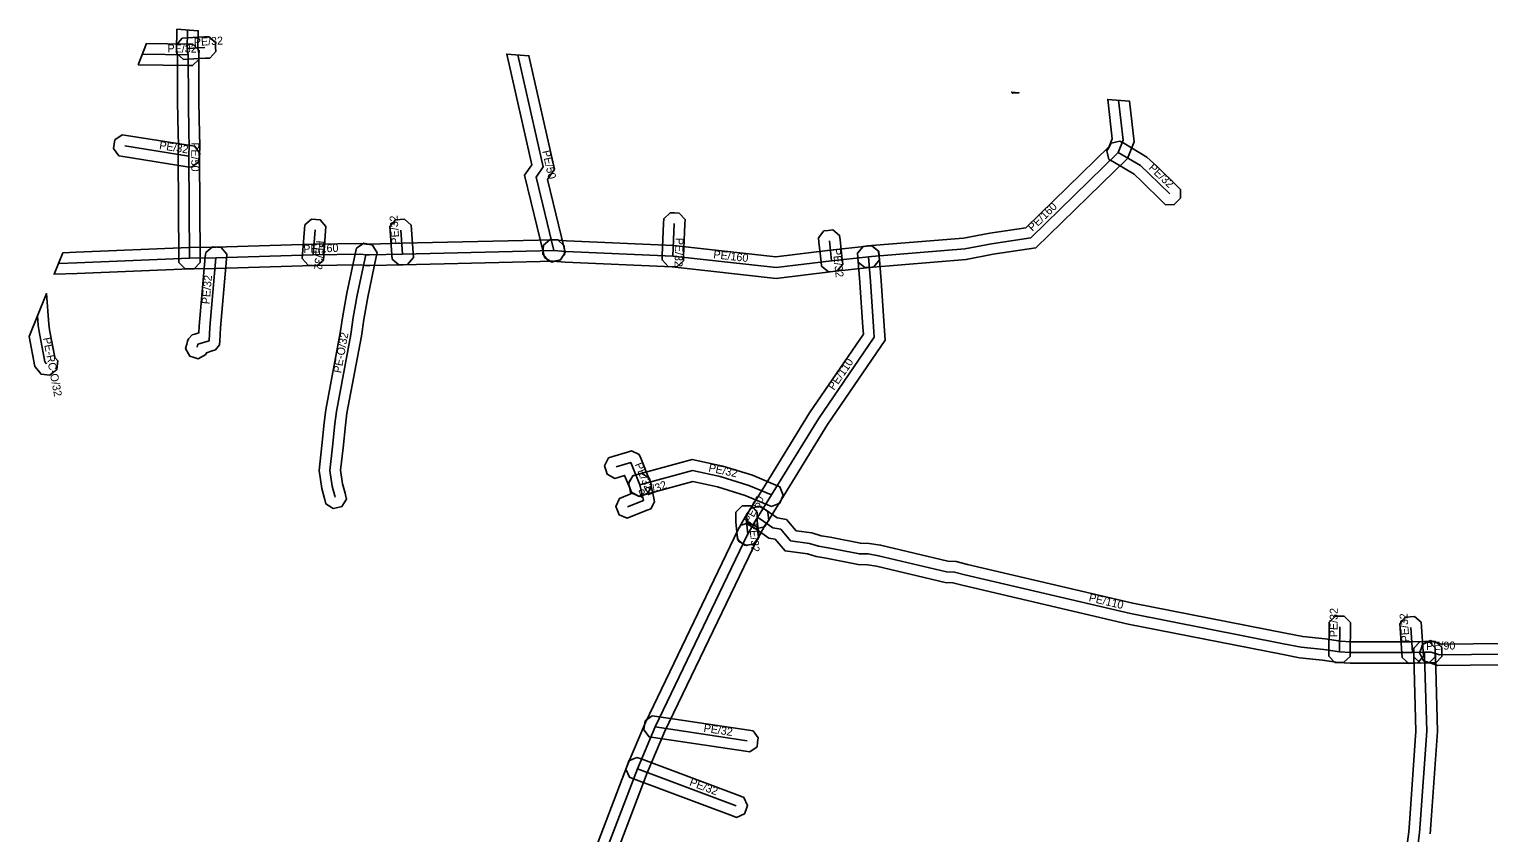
# Model space of a CAD drawing. Extents: x -772893 to -772575, y -1033735 to -1033288.
# Drawn here: x -772863.9 to -772727.1, y -1033363.2 to -1033287.9 of the extents above; entities that cross this region are included whole.
import ezdxf

# ---------------------------------------------------------------- set-up
doc = ezdxf.new("R2010")
doc.units = 0
for name, color, linetype in [('1', 7, 'Continuous'), ('24', 7, 'Continuous'), ('30', 7, 'Continuous')]:
    doc.layers.add(name, color=color, linetype=linetype)

msp = doc.modelspace()

# ---------------------------------------------------------------- linework, layer by layer
at = {"layer": '1'}
for points in [[(-772849.52, -1033288.74), (-772849.1, -1033288.72), (-772847.45, -1033288.63), (-772847.04, -1033288.61), (-772846.42, -1033289.16), (-772846.4, -1033289.58), (-772846.38, -1033289.99), (-772846.93, -1033290.61), (-772847.35, -1033290.63), (-772849, -1033290.72), (-772849.41, -1033290.74), (-772850.03, -1033290.19), (-772850.05, -1033289.77), (-772850.07, -1033289.36)], [(-772850.02, -1033288.08), (-772850.02, -1033287.9), (-772848.02, -1033288.05), (-772848.02, -1033288.12), (-772848.05, -1033289.65), (-772847.96, -1033290.22), (-772847.96, -1033294.7), (-772847.9, -1033297.66), (-772847.89, -1033298.75), (-772847.92, -1033299.8), (-772847.84, -1033309.33), (-772847.84, -1033309.75), (-772848.42, -1033310.34), (-772848.83, -1033310.34), (-772849.25, -1033310.34), (-772849.84, -1033309.76), (-772849.84, -1033309.35), (-772849.92, -1033299.78), (-772849.89, -1033298.73), (-772849.9, -1033297.68), (-772849.96, -1033294.72), (-772849.96, -1033290.38), (-772850.05, -1033289.79)], [(-772853.66, -1033291.24), (-772852.86, -1033289.25), (-772848.95, -1033289.3), (-772848.53, -1033289.31), (-772847.95, -1033289.9), (-772847.96, -1033290.31), (-772847.96, -1033290.73), (-772848.56, -1033291.31), (-772848.97, -1033291.3)], [(-772816.78, -1033300.6), (-772819.12, -1033290.23), (-772817.04, -1033290.39), (-772814.64, -1033301), (-772815.29, -1033301.97), (-772813.75, -1033308.41), (-772813.65, -1033308.81), (-772814.08, -1033309.52), (-772814.49, -1033309.61), (-772814.89, -1033309.71), (-772815.59, -1033309.28), (-772815.69, -1033308.87), (-772817.45, -1033301.57)], [(-772771.7, -1033293.9), (-772771.81, -1033293.8), (-772771.13, -1033293.86), (-772771.29, -1033293.87)], [(-772762.39, -1033298.16), (-772762.81, -1033294.48), (-772760.77, -1033294.64), (-772760.34, -1033298.44), (-772760.97, -1033300.02), (-772769.54, -1033308.38), (-772773.53, -1033308.99), (-772776.06, -1033309.46), (-772785.15, -1033310.21), (-772785.56, -1033310.24), (-772786.19, -1033309.71), (-772786.23, -1033309.29), (-772786.26, -1033308.88), (-772785.73, -1033308.25), (-772785.31, -1033308.21), (-772776.32, -1033307.47), (-772773.86, -1033307.02), (-772770.48, -1033306.5), (-772762.67, -1033298.88)], [(-772848.67, -1033300.84), (-772849.08, -1033300.78), (-772855.07, -1033299.83), (-772855.48, -1033299.76), (-772855.96, -1033299.09), (-772855.9, -1033298.68), (-772855.83, -1033298.27), (-772855.16, -1033297.79), (-772854.75, -1033297.85), (-772848.76, -1033298.8), (-772848.35, -1033298.87), (-772847.87, -1033299.54), (-772847.93, -1033299.95), (-772848, -1033300.36)], [(-772761.67, -1033298.38), (-772761.31, -1033298.59), (-772759.14, -1033299.88), (-772758.22, -1033300.74), (-772756.3, -1033302.61), (-772756, -1033302.91), (-772755.99, -1033303.73), (-772756.29, -1033304.03), (-772756.58, -1033304.33), (-772757.4, -1033304.34), (-772757.7, -1033304.05), (-772759.6, -1033302.18), (-772760.34, -1033301.48), (-772762.33, -1033300.31), (-772762.69, -1033300.1), (-772762.89, -1033299.3), (-772762.68, -1033298.94), (-772762.47, -1033298.58)], [(-772802.41, -1033305.74), (-772802.43, -1033306.16), (-772802.56, -1033309.19), (-772802.57, -1033309.6), (-772803.18, -1033310.16), (-772803.6, -1033310.15), (-772804.01, -1033310.13), (-772804.57, -1033309.52), (-772804.56, -1033309.1), (-772804.43, -1033306.07), (-772804.41, -1033305.66), (-772803.8, -1033305.1), (-772803.39, -1033305.11), (-772802.97, -1033305.13)], [(-772836.06, -1033306.37), (-772836.09, -1033306.79), (-772836.25, -1033309.11), (-772836.28, -1033309.53), (-772836.91, -1033310.07), (-772837.32, -1033310.04), (-772837.73, -1033310.01), (-772838.28, -1033309.39), (-772838.25, -1033308.97), (-772838.08, -1033306.64), (-772838.05, -1033306.23), (-772837.43, -1033305.69), (-772837.01, -1033305.72), (-772836.6, -1033305.75)], [(-772829.86, -1033309.44), (-772829.89, -1033309.03), (-772830.04, -1033306.8), (-772830.07, -1033306.39), (-772829.53, -1033305.76), (-772829.11, -1033305.73), (-772828.7, -1033305.71), (-772828.07, -1033306.25), (-772828.05, -1033306.66), (-772827.89, -1033308.89), (-772827.86, -1033309.3), (-772828.41, -1033309.93), (-772828.82, -1033309.96), (-772829.23, -1033309.99)], [(-772789.63, -1033310.11), (-772789.67, -1033309.7), (-772789.88, -1033307.85), (-772789.92, -1033307.44), (-772789.4, -1033306.79), (-772788.99, -1033306.75), (-772788.58, -1033306.7), (-772787.93, -1033307.22), (-772787.89, -1033307.63), (-772787.69, -1033309.49), (-772787.64, -1033309.9), (-772788.16, -1033310.54), (-772788.57, -1033310.59), (-772788.98, -1033310.63)], [(-772859.38, -1033310.8), (-772861.53, -1033310.86), (-772860.71, -1033308.84), (-772859.45, -1033308.8), (-772848.87, -1033308.34), (-772846.39, -1033308.32), (-772837.27, -1033308.04), (-772832.73, -1033307.97), (-772832.26, -1033308.03), (-772831.98, -1033308.03), (-772828.91, -1033307.96), (-772814.74, -1033307.64), (-772814.33, -1033307.63), (-772813.73, -1033308.2), (-772813.72, -1033308.62), (-772813.71, -1033309.03), (-772814.28, -1033309.63), (-772814.7, -1033309.64), (-772828.87, -1033309.96), (-772831.96, -1033310.03), (-772832.38, -1033310.03), (-772832.84, -1033309.97), (-772837.23, -1033310.04), (-772846.35, -1033310.32), (-772848.81, -1033310.34)], [(-772831.26, -1033308.84), (-772831.34, -1033309.24), (-772832.15, -1033313), (-772832.51, -1033315.08), (-772832.74, -1033316.65), (-772834.09, -1033323.87), (-772834.24, -1033324.99), (-772834.46, -1033327.12), (-772834.69, -1033329.21), (-772834.5, -1033330.5), (-772834.25, -1033331.36), (-772834.22, -1033331.52), (-772834.12, -1033331.92), (-772834.56, -1033332.62), (-772834.96, -1033332.71), (-772835.37, -1033332.81), (-772836.07, -1033332.37), (-772836.16, -1033331.96), (-772836.19, -1033331.86), (-772836.46, -1033330.92), (-772836.71, -1033329.25), (-772836.44, -1033326.9), (-772836.22, -1033324.77), (-772836.07, -1033323.55), (-772834.72, -1033316.33), (-772834.49, -1033314.76), (-772834.11, -1033312.62), (-772833.3, -1033308.82), (-772833.21, -1033308.42), (-772832.52, -1033307.96), (-772832.11, -1033308.05), (-772831.7, -1033308.14)], [(-772784.71, -1033310.16), (-772785.12, -1033310.21), (-772788.56, -1033310.59), (-772793.89, -1033311.24), (-772803.63, -1033310.15), (-772813.65, -1033309.74), (-772814.81, -1033309.64), (-772815.22, -1033309.6), (-772815.75, -1033308.97), (-772815.72, -1033308.55), (-772815.68, -1033308.14), (-772815.05, -1033307.61), (-772814.63, -1033307.64), (-772813.53, -1033307.74), (-772803.48, -1033308.15), (-772793.9, -1033309.23), (-772788.8, -1033308.6), (-772785.34, -1033308.22), (-772784.93, -1033308.17), (-772784.28, -1033308.69), (-772784.24, -1033309.1), (-772784.19, -1033309.51)], [(-772846.71, -1033318.04), (-772847.25, -1033318.21), (-772847.3, -1033318.37), (-772848.03, -1033318.77), (-772848.42, -1033318.65), (-772848.82, -1033318.53), (-772849.22, -1033317.8), (-772849.1, -1033317.41), (-772849.02, -1033317.14), (-772848.95, -1033316.9), (-772848.6, -1033316.54), (-772848.36, -1033316.47), (-772847.97, -1033316.34), (-772847.94, -1033315.73), (-772847.37, -1033309.23), (-772847.33, -1033308.82), (-772846.7, -1033308.29), (-772846.28, -1033308.32), (-772845.87, -1033308.36), (-772845.34, -1033308.99), (-772845.37, -1033309.41), (-772845.94, -1033315.87), (-772846.01, -1033317.14), (-772846.03, -1033317.46), (-772846.41, -1033317.95)], [(-772784.27, -1033308.72), (-772784.23, -1033309.13), (-772784.04, -1033311.48), (-772783.75, -1033315.68), (-772783.66, -1033317.03), (-772789.08, -1033324.94), (-772793.45, -1033332.05), (-772794.76, -1033334.18), (-772794.98, -1033334.53), (-772795.78, -1033334.72), (-772796.14, -1033334.5), (-772796.49, -1033334.28), (-772796.68, -1033333.48), (-772796.46, -1033333.12), (-772795.15, -1033331.01), (-772790.76, -1033323.85), (-772785.7, -1033316.47), (-772785.75, -1033315.82), (-772786.03, -1033311.63), (-772786.23, -1033309.29), (-772786.26, -1033308.88), (-772785.73, -1033308.25), (-772785.31, -1033308.21), (-772784.9, -1033308.18)], [(-772863.33, -1033319.49), (-772863.87, -1033316.7), (-772862.25, -1033312.66), (-772862.03, -1033315.54), (-772861.95, -1033316.06), (-772861.45, -1033318.63), (-772861.45, -1033318.64), (-772861.19, -1033318.96), (-772861.28, -1033319.78), (-772861.6, -1033320.04), (-772861.93, -1033320.3), (-772862.75, -1033320.21), (-772863.01, -1033319.89)], [(-772807.41, -1033331.35), (-772807.57, -1033330.97), (-772808.08, -1033329.7), (-772808.59, -1033329.86), (-772808.98, -1033329.98), (-772809.72, -1033329.59), (-772809.84, -1033329.19), (-772809.96, -1033328.8), (-772809.57, -1033328.06), (-772809.17, -1033327.94), (-772807.79, -1033327.52), (-772807.42, -1033327.41), (-772806.72, -1033327.74), (-772806.57, -1033328.1), (-772805.71, -1033330.21), (-772805.56, -1033330.6), (-772805.88, -1033331.36), (-772806.26, -1033331.52), (-772806.65, -1033331.67)], [(-772794.31, -1033332.61), (-772794.69, -1033332.45), (-772796.78, -1033331.57), (-772799.38, -1033330.77), (-772801.68, -1033330.28), (-772806.38, -1033331.56), (-772806.78, -1033331.66), (-772807.5, -1033331.25), (-772807.6, -1033330.85), (-772807.71, -1033330.45), (-772807.3, -1033329.73), (-772806.9, -1033329.62), (-772801.74, -1033328.22), (-772798.88, -1033328.83), (-772796.1, -1033329.69), (-772793.91, -1033330.61), (-772793.53, -1033330.77), (-772793.22, -1033331.54), (-772793.38, -1033331.92), (-772793.54, -1033332.3)], [(-772805.75, -1033329.97), (-772805.66, -1033330.37), (-772805.34, -1033331.82), (-772805.26, -1033332.18), (-772805.61, -1033332.84), (-772805.95, -1033332.97), (-772807.45, -1033333.56), (-772807.84, -1033333.71), (-772808.6, -1033333.38), (-772808.75, -1033333), (-772808.9, -1033332.61), (-772808.57, -1033331.85), (-772808.19, -1033331.7), (-772807.48, -1033331.42), (-772807.62, -1033330.81), (-772807.71, -1033330.4), (-772807.26, -1033329.7), (-772806.86, -1033329.61), (-772806.45, -1033329.52)], [(-772797.49, -1033335.71), (-772797.53, -1033335.3), (-772797.64, -1033334.07), (-772797.64, -1033333.56), (-772797.64, -1033333.15), (-772797.05, -1033332.56), (-772796.64, -1033332.56), (-772796.23, -1033332.56), (-772795.64, -1033333.15), (-772795.64, -1033333.56), (-772795.64, -1033333.97), (-772795.53, -1033335.12), (-772795.5, -1033335.53), (-772796.03, -1033336.17), (-772796.44, -1033336.21), (-772796.85, -1033336.24)], [(-772794.57, -1033333.95), (-772794.83, -1033334.28), (-772794.93, -1033334.4), (-772795.41, -1033335.27), (-772795.66, -1033335.71), (-772795.87, -1033336.07), (-772796.67, -1033336.28), (-772797.03, -1033336.08), (-772797.39, -1033335.87), (-772797.6, -1033335.07), (-772797.4, -1033334.71), (-772797.15, -1033334.28), (-772796.6, -1033333.28), (-772796.39, -1033333.03), (-772796.13, -1033332.7), (-772795.31, -1033332.61), (-772794.98, -1033332.87), (-772794.66, -1033333.13)], [(-772795.49, -1033332.57), (-772795.13, -1033332.77), (-772794.8, -1033332.96), (-772793.78, -1033333.67), (-772792.92, -1033333.83), (-772792.01, -1033334.89), (-772790.52, -1033335.09), (-772789.67, -1033335.35), (-772788.83, -1033335.49), (-772785.98, -1033336.06), (-772785.16, -1033336.07), (-772784.09, -1033336.23), (-772777.78, -1033337.74), (-772777.02, -1033337.75), (-772775.94, -1033338.05), (-772760.46, -1033341.68), (-772746.14, -1033344.48), (-772744.54, -1033344.8), (-772742.44, -1033345.02), (-772741, -1033345.23), (-772740.03, -1033345.28), (-772734.24, -1033345.28), (-772733.13, -1033345.27), (-772732.71, -1033345.27), (-772732.12, -1033345.85), (-772732.12, -1033346.27), (-772732.12, -1033346.68), (-772732.7, -1033347.27), (-772733.11, -1033347.27), (-772734.24, -1033347.28), (-772740.08, -1033347.28), (-772741.2, -1033347.23), (-772742.69, -1033347.01), (-772744.83, -1033346.78), (-772746.52, -1033346.45), (-772760.88, -1033343.63), (-772776.44, -1033339.99), (-772777.31, -1033339.75), (-772778.03, -1033339.74), (-772784.48, -1033338.2), (-772785.32, -1033338.07), (-772786.18, -1033338.06), (-772789.19, -1033337.46), (-772790.13, -1033337.3), (-772790.95, -1033337.05), (-772793.04, -1033336.77), (-772793.98, -1033335.67), (-772794.57, -1033335.57), (-772795.86, -1033334.65), (-772796.09, -1033334.53), (-772796.46, -1033334.33), (-772796.69, -1033333.53), (-772796.49, -1033333.17), (-772796.29, -1033332.8)], [(-772742.1, -1033346.63), (-772742.1, -1033346.22), (-772742.07, -1033343.88), (-772742.07, -1033343.46), (-772741.47, -1033342.89), (-772741.06, -1033342.89), (-772740.64, -1033342.9), (-772740.07, -1033343.49), (-772740.07, -1033343.9), (-772740.1, -1033346.24), (-772740.1, -1033346.66), (-772740.7, -1033347.23), (-772741.11, -1033347.23), (-772741.53, -1033347.22)], [(-772735.21, -1033346.77), (-772735.24, -1033346.35), (-772735.41, -1033344.01), (-772735.44, -1033343.6), (-772734.9, -1033342.97), (-772734.48, -1033342.94), (-772734.07, -1033342.91), (-772733.44, -1033343.46), (-772733.41, -1033343.87), (-772733.24, -1033346.21), (-772733.21, -1033346.62), (-772733.76, -1033347.25), (-772734.17, -1033347.28), (-772734.58, -1033347.31)], [(-772733.55, -1033345.28), (-772733.14, -1033345.27), (-772732.8, -1033345.27), (-772732.52, -1033345.26), (-772732.1, -1033345.25), (-772731.51, -1033345.83), (-772731.5, -1033346.24), (-772731.49, -1033346.66), (-772732.07, -1033347.25), (-772732.48, -1033347.26), (-772732.76, -1033347.27), (-772733.1, -1033347.27), (-772733.51, -1033347.28), (-772734.11, -1033346.71), (-772734.12, -1033346.29), (-772734.13, -1033345.88)], [(-772805.48, -1033352.21), (-772805.07, -1033352.27), (-772796.45, -1033353.56), (-772796.04, -1033353.62), (-772795.55, -1033354.29), (-772795.61, -1033354.7), (-772795.67, -1033355.11), (-772796.34, -1033355.6), (-772796.75, -1033355.54), (-772805.37, -1033354.25), (-772805.78, -1033354.19), (-772806.27, -1033353.52), (-772806.21, -1033353.11), (-772806.15, -1033352.7)], [(-772806.92, -1033356.11), (-772806.53, -1033356.25), (-772797.28, -1033359.71), (-772796.89, -1033359.86), (-772796.55, -1033360.61), (-772796.69, -1033361), (-772796.84, -1033361.39), (-772797.59, -1033361.73), (-772797.98, -1033361.59), (-772807.23, -1033358.13), (-772807.62, -1033357.98), (-772807.96, -1033357.23), (-772807.82, -1033356.84), (-772807.67, -1033356.45)]]:
    msp.add_lwpolyline(points, close=True, dxfattribs=at)
for points in [[(-772813.06, -1033370.57), (-772807.81, -1033356.82), (-772806.13, -1033352.85), (-772797.43, -1033334.78), (-772797.4, -1033334.71), (-772797.19, -1033334.35), (-772796.39, -1033334.14), (-772796.03, -1033334.34), (-772795.67, -1033334.55), (-772795.46, -1033335.35), (-772795.66, -1033335.71), (-772795.66, -1033335.71), (-772804.31, -1033353.67), (-772805.95, -1033357.56), (-772811.1, -1033371.05)], [(-772734.71, -1033364.01), (-772734.59, -1033363.08), (-772734.54, -1033362.28), (-772733.93, -1033353.65), (-772734.11, -1033346.6), (-772734.12, -1033346.3), (-772734.13, -1033345.88), (-772733.56, -1033345.28), (-772733.14, -1033345.27), (-772732.73, -1033345.26), (-772732.13, -1033345.84), (-772732.12, -1033346.25), (-772732.11, -1033346.55), (-772731.92, -1033353.69), (-772732.54, -1033362.42), (-772732.6, -1033363.28)], [(-772707.62, -1033347.27), (-772731.89, -1033347.52), (-772732.82, -1033347.21), (-772733.21, -1033347.07), (-772733.58, -1033346.33), (-772733.45, -1033345.94), (-772733.31, -1033345.55), (-772732.57, -1033345.18), (-772732.18, -1033345.31), (-772731.57, -1033345.52), (-772707.68, -1033345.27)]]:
    msp.add_lwpolyline(points, dxfattribs=at)
at = {"layer": '24'}
for points in [[(-772849.02, -1033287.98), (-772849.02, -1033288.1), (-772849.05, -1033289.72), (-772848.96, -1033290.3), (-772848.95, -1033294.71), (-772848.9, -1033297.67), (-772848.89, -1033298.74), (-772848.92, -1033299.79), (-772848.84, -1033309.34)], [(-772848.96, -1033290.3), (-772853.26, -1033290.25)], [(-772849.05, -1033289.72), (-772847.4, -1033289.63)], [(-772814.72, -1033308.64), (-772816.37, -1033301.77), (-772815.71, -1033300.8), (-772818.08, -1033290.31)], [(-772761.79, -1033294.56), (-772761.36, -1033298.3), (-772761.82, -1033299.45), (-772770.01, -1033307.44), (-772773.69, -1033308.01), (-772776.19, -1033308.47), (-772784.93, -1033309.19), (-772785.23, -1033309.21)], [(-772848.92, -1033299.79), (-772854.91, -1033298.84)], [(-772761.82, -1033299.45), (-772759.74, -1033300.68), (-772758.91, -1033301.46), (-772757, -1033303.33)], [(-772837.08, -1033306.71), (-772837.25, -1033309.04)], [(-772828.89, -1033308.96), (-772829.04, -1033306.73)], [(-772803.43, -1033306.11), (-772803.56, -1033309.15)], [(-772788.68, -1033309.59), (-772788.88, -1033307.74)], [(-772814.72, -1033308.64), (-772828.89, -1033308.96), (-772831.97, -1033309.03), (-772832.32, -1033309.03), (-772832.79, -1033308.97), (-772837.25, -1033309.04), (-772846.37, -1033309.32), (-772848.84, -1033309.34), (-772859.41, -1033309.8), (-772861.12, -1033309.85)], [(-772846.37, -1033309.32), (-772846.94, -1033315.8), (-772847.01, -1033317.09), (-772848.06, -1033317.42), (-772848.14, -1033317.69)], [(-772832.32, -1033309.03), (-772833.13, -1033312.81), (-772833.5, -1033314.92), (-772833.73, -1033316.49), (-772835.08, -1033323.71), (-772835.23, -1033324.88), (-772835.45, -1033327.01), (-772835.7, -1033329.23), (-772835.48, -1033330.71), (-772835.22, -1033331.61), (-772835.19, -1033331.74)], [(-772785.23, -1033309.21), (-772788.68, -1033309.59), (-772793.89, -1033310.24), (-772803.56, -1033309.15), (-772813.59, -1033308.74), (-772814.72, -1033308.64)], [(-772785.23, -1033309.21), (-772785.04, -1033311.55), (-772784.75, -1033315.75), (-772784.68, -1033316.75), (-772789.92, -1033324.39), (-772794.3, -1033331.53), (-772795.61, -1033333.65)], [(-772863.09, -1033314.76), (-772863.02, -1033315.65), (-772862.94, -1033316.22), (-772862.39, -1033319.06), (-772862.23, -1033319.26)], [(-772806.64, -1033330.59), (-772807.5, -1033328.48), (-772808.88, -1033328.9)], [(-772794.3, -1033331.53), (-772796.44, -1033330.63), (-772799.13, -1033329.8), (-772801.71, -1033329.25), (-772806.64, -1033330.59)], [(-772806.64, -1033330.59), (-772806.32, -1033332.04), (-772807.82, -1033332.63)], [(-772796.53, -1033335.21), (-772796.64, -1033334.02), (-772796.64, -1033333.56)], [(-772795.61, -1033333.65), (-772795.76, -1033333.84), (-772796.28, -1033334.78), (-772796.53, -1033335.21)], [(-772795.61, -1033333.65), (-772795.33, -1033333.81), (-772794.18, -1033334.62), (-772793.45, -1033334.75), (-772792.53, -1033335.83), (-772790.74, -1033336.07), (-772789.9, -1033336.33), (-772789.01, -1033336.48), (-772786.08, -1033337.06), (-772785.24, -1033337.06), (-772784.28, -1033337.22), (-772777.91, -1033338.74), (-772777.16, -1033338.75), (-772776.19, -1033339.02), (-772760.67, -1033342.65), (-772746.33, -1033345.47), (-772744.68, -1033345.79), (-772742.56, -1033346.01), (-772741.1, -1033346.23), (-772740.05, -1033346.28), (-772734.24, -1033346.28), (-772733.12, -1033346.27)], [(-772796.53, -1033335.21), (-772796.55, -1033335.24), (-772805.22, -1033353.26), (-772806.88, -1033357.19), (-772812.08, -1033370.81), (-772812.21, -1033371.86), (-772812.6, -1033376.52), (-772813.13, -1033379.79), (-772814.63, -1033386.94), (-772814.98, -1033388.68), (-772816.12, -1033397.89), (-772816.12, -1033398.37), (-772817.22, -1033410.19), (-772817.32, -1033410.45), (-772819.33, -1033421.11), (-772819.89, -1033426.16), (-772820.1, -1033427.55), (-772821.71, -1033436.83)], [(-772575.05, -1033337.94), (-772595.98, -1033340.29), (-772597.85, -1033341.12), (-772600.09, -1033342.24), (-772610.22, -1033343.53), (-772622.65, -1033344.2), (-772632.69, -1033344.54), (-772636.51, -1033344.67), (-772637.23, -1033344.78), (-772648.28, -1033345.38), (-772667.77, -1033346.11), (-772668.56, -1033346.21), (-772679.53, -1033346.14), (-772683.05, -1033346.23), (-772689.18, -1033346.38), (-772690.84, -1033346.47), (-772701.27, -1033346.26), (-772703.45, -1033346.3), (-772704.4, -1033346.29), (-772706.87, -1033346.23), (-772707.65, -1033346.27), (-772731.73, -1033346.52), (-772732.5, -1033346.26)], [(-772741.1, -1033346.23), (-772741.07, -1033343.89)], [(-772734.24, -1033346.28), (-772734.41, -1033343.94)], [(-772733.12, -1033346.27), (-772733.11, -1033346.58), (-772732.92, -1033353.67), (-772733.54, -1033362.35), (-772733.6, -1033363.18), (-772733.72, -1033364.14), (-772734.62, -1033371.2), (-772734.81, -1033372.68), (-772734.95, -1033373.21), (-772735, -1033373.69), (-772736.35, -1033385.14), (-772736.71, -1033391.39), (-772737.82, -1033402.46), (-772737.92, -1033403.95), (-772738.16, -1033405.21), (-772738.27, -1033406.3), (-772738.37, -1033407.46), (-772738.63, -1033410.56), (-772739.63, -1033420.59), (-772740.65, -1033431.65), (-772741.28, -1033437.44)], [(-772733.12, -1033346.27), (-772732.78, -1033346.27), (-772732.5, -1033346.26)], [(-772805.22, -1033353.26), (-772796.6, -1033354.55)], [(-772806.88, -1033357.19), (-772797.63, -1033360.65)]]:
    msp.add_lwpolyline(points, dxfattribs=at)

# ---------------------------------------------------------------- texts
at = {"layer": '30'}
for s, rotation, p in [('PE/32', 3.1221, (-772848.42, -1033289.48)), ('PE/32', 359.3293, (-772850.91, -1033290.07)), ('PE/32', 350.9881, (-772851.72, -1033299.12)), ('PE/50', 270.3752, (-772848.69, -1033298.51)), ('PE/50', 282.7184, (-772815.8, -1033299.33)), ('PE/32', 316.7788, (-772759.03, -1033300.96)), ('PE/160', 44.2848, (-772769.85, -1033306.89)), ('PE/32', 93.9576, (-772829.17, -1033308.05)), ('PE/160', 1.7399, (-772838.17, -1033308.86)), ('PE/32', 265.9214, (-772836.97, -1033307.68)), ('PE/32', 267.6031, (-772803.29, -1033307.43)), ('PE/160', 353.5603, (-772799.79, -1033309.35)), ('PE/32', 276.2214, (-772788.58, -1033308.47)), ('PE/32', 84.981, (-772846.97, -1033313.69)), ('PE-RC-O/32', 280.9603, (-772862.58, -1033316.84)), ('PE-O/32', 79.4091, (-772834.65, -1033320.16)), ('PE/110', 55.5431, (-772788.46, -1033321.78)), ('PE/32', 292.175, (-772807.14, -1033328.67)), ('PE/32', 347.9659, (-772800.26, -1033329.32)), ('PE/32', 21.4714, (-772806.58, -1033331.86)), ('PE/50', 61.0131, (-772796.31, -1033334.26)), ('PE/32', 275.2291, (-772796.41, -1033334.19)), ('PE/110', 346.8303, (-772764.63, -1033341.48)), ('PE/32', 89.2655, (-772741.28, -1033344.86)), ('PE/32', 94.1552, (-772734.53, -1033345.31)), ('PE/90', 1.1899, (-772732.96, -1033346.06)), ('PE/32', 351.4887, (-772800.71, -1033353.71)), ('PE/32', 339.4915, (-772802.06, -1033358.72))]:
    msp.add_text(s, height=0.75, rotation=rotation, dxfattribs=at).set_placement(p)

doc.saveas('drawing.dxf')
